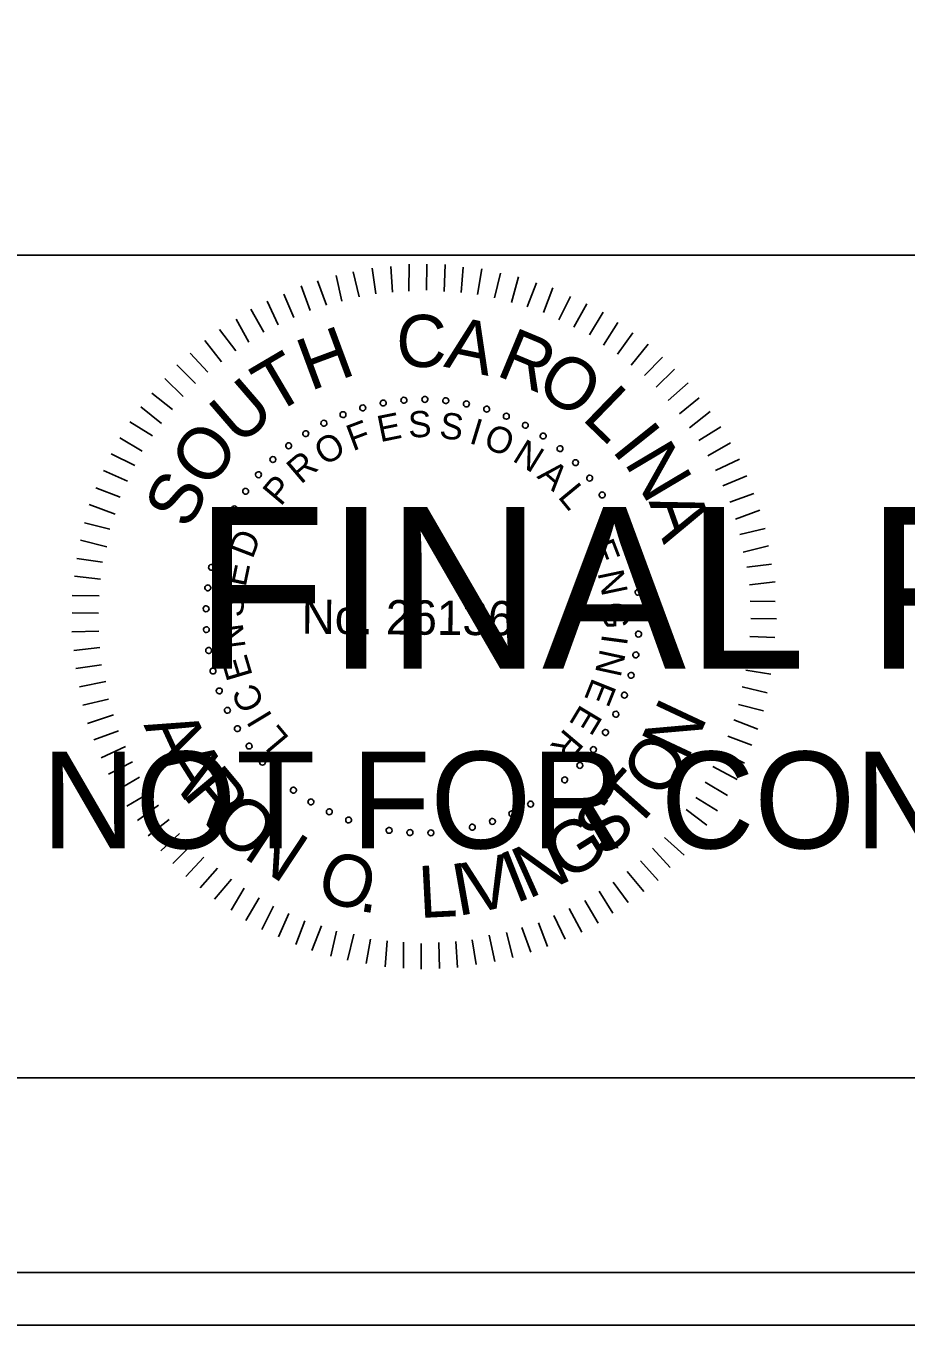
# Model space of a CAD drawing. Extents: x 967 to 1326, y 964 to 2304.
# Drawn here: x 1170.56 to 1189.3, y 1803.72 to 1831.36 of the extents above; entities that cross this region are included whole.
import ezdxf

# ---------------------------------------------------------------- set-up
doc = ezdxf.new("R2010")
doc.units = 0
for name, color, linetype in [('RD_PD_PaveShd', 7, 'Continuous'), ('RD_XS_Misc_Line', 7, 'Continuous'), ('RD_XS_PaveOvlay', 7, 'Continuous'), ('RD_XS_TX_Elev_EX', 7, 'Continuous'), ('RD_XS_TX_Elev_PR', 7, 'Continuous')]:
    doc.layers.add(name, color=color, linetype=linetype)

msp = doc.modelspace()

# ---------------------------------------------------------------- linework, layer by layer
at = {"layer": 'RD_PD_PaveShd'}
for p, q in [((996.114, 1826.486), (1323.886, 1826.486)), ((1323.886, 1808.983), (996.114, 1808.983))]:
    msp.add_line(p, q, dxfattribs=at)
at = {"layer": 'RD_XS_Misc_Line'}
for p, q in [((1178.01, 1825.663), (1177.93, 1826.209)), ((1178.364, 1825.699), (1178.33, 1826.244)), ((1178.717, 1825.719), (1178.722, 1826.295)), ((1179.093, 1825.739), (1179.098, 1826.292)), ((1179.469, 1825.713), (1179.489, 1826.288)), ((1179.829, 1825.687), (1179.872, 1826.231)), ((1180.174, 1825.646), (1180.271, 1826.19)), ((1176.964, 1825.419), (1176.769, 1825.935)), ((1177.287, 1825.508), (1177.169, 1826.054)), ((1177.657, 1825.597), (1177.53, 1826.128)), ((1180.535, 1825.573), (1180.662, 1826.102)), ((1180.902, 1825.478), (1181.045, 1826.022)), ((1181.231, 1825.384), (1181.428, 1825.896)), ((1176.264, 1825.156), (1176.053, 1825.657)), ((1176.61, 1825.306), (1176.423, 1825.83)), ((1181.584, 1825.265), (1181.78, 1825.786)), ((1181.905, 1825.109), (1182.154, 1825.606)), ((1175.624, 1824.846), (1175.352, 1825.332)), ((1175.933, 1825.005), (1175.699, 1825.506)), ((1182.226, 1824.953), (1182.506, 1825.45)), ((1175.308, 1824.634), (1175.036, 1825.12)), ((1182.562, 1824.789), (1182.85, 1825.27)), ((1175.03, 1824.445), (1174.681, 1824.9)), ((1182.86, 1824.572), (1183.163, 1825.053)), ((1183.158, 1824.378), (1183.484, 1824.828)), ((1174.729, 1824.217), (1174.372, 1824.665)), ((1183.447, 1824.145), (1183.811, 1824.587)), ((1174.435, 1823.997), (1174.062, 1824.399)), ((1183.729, 1823.92), (1184.116, 1824.316)), ((1174.172, 1823.753), (1173.776, 1824.148)), ((1183.98, 1823.672), (1184.368, 1824.061)), ((1173.909, 1823.479), (1173.52, 1823.858)), ((1184.232, 1823.394), (1184.657, 1823.767)), ((1173.684, 1823.197), (1173.242, 1823.546)), ((1184.475, 1823.108), (1184.892, 1823.45)), ((1173.451, 1822.9), (1173.009, 1823.256)), ((1184.687, 1822.807), (1185.128, 1823.156)), ((1173.257, 1822.64), (1172.776, 1822.936)), ((1173.039, 1822.312), (1172.559, 1822.6)), ((1184.885, 1822.544), (1185.355, 1822.832)), ((1185.081, 1822.213), (1185.56, 1822.493)), ((1172.883, 1822.006), (1172.379, 1822.256)), ((1185.24, 1821.904), (1185.756, 1822.145)), ((1172.727, 1821.677), (1172.215, 1821.904)), ((1185.399, 1821.573), (1185.907, 1821.791)), ((1172.571, 1821.333), (1172.051, 1821.53)), ((1185.549, 1821.226), (1186.057, 1821.414)), ((1172.461, 1820.974), (1171.91, 1821.178)), ((1185.669, 1820.865), (1186.185, 1821.06)), ((1172.351, 1820.652), (1171.807, 1820.787)), ((1185.759, 1820.541), (1186.297, 1820.667)), ((1172.286, 1820.276), (1171.727, 1820.419)), ((1185.832, 1820.165), (1186.371, 1820.298)), ((1172.191, 1819.955), (1171.647, 1820.029)), ((1185.906, 1819.842), (1186.436, 1819.906)), ((1172.15, 1819.587), (1171.598, 1819.653)), ((1185.964, 1819.473), (1186.51, 1819.53)), ((1172.124, 1819.234), (1171.548, 1819.239)), ((1185.977, 1819.12), (1186.514, 1819.115)), ((1172.105, 1818.866), (1171.545, 1818.871)), ((1185.997, 1818.751), (1186.542, 1818.747)), ((1172.118, 1818.482), (1171.542, 1818.471)), ((1185.971, 1818.368), (1186.508, 1818.348)), ((1172.138, 1818.136), (1171.585, 1818.072)), ((1185.952, 1818.022), (1186.497, 1817.949)), ((1172.173, 1817.768), (1171.627, 1817.688)), ((1185.888, 1817.655), (1186.417, 1817.566)), ((1172.262, 1817.414), (1171.701, 1817.296)), ((1185.808, 1817.302), (1186.345, 1817.175)), ((1172.321, 1817.037), (1171.774, 1816.911)), ((1185.729, 1816.926), (1186.265, 1816.792)), ((1172.425, 1816.707), (1171.871, 1816.519)), ((1185.634, 1816.597), (1186.146, 1816.401)), ((1172.53, 1816.36), (1172.007, 1816.173)), ((1185.508, 1816.253), (1186.013, 1816.057)), ((1172.681, 1816.029), (1172.165, 1815.788)), ((1172.831, 1815.705), (1172.323, 1815.441)), ((1185.352, 1815.924), (1185.857, 1815.675)), ((1185.188, 1815.603), (1185.7, 1815.33)), ((1172.982, 1815.374), (1172.497, 1815.094)), ((1185.024, 1815.274), (1185.498, 1814.987)), ((1173.194, 1815.042), (1172.709, 1814.762)), ((1184.822, 1814.946), (1185.288, 1814.658)), ((1173.384, 1814.78), (1172.936, 1814.453)), ((1184.62, 1814.687), (1185.055, 1814.353)), ((1173.612, 1814.478), (1173.164, 1814.129)), ((1184.403, 1814.389), (1184.814, 1814.033)), ((1173.832, 1814.177), (1173.437, 1813.812)), ((1184.155, 1814.092), (1184.574, 1813.72)), ((1174.091, 1813.945), (1173.689, 1813.541)), ((1183.899, 1813.864), (1184.28, 1813.454)), ((1174.35, 1813.674), (1173.97, 1813.263)), ((1183.644, 1813.597), (1184.024, 1813.18)), ((1174.64, 1813.442), (1174.275, 1813.022)), ((1174.937, 1813.209), (1174.58, 1812.782)), ((1183.358, 1813.37), (1183.715, 1812.944)), ((1175.212, 1813.014), (1174.932, 1812.549)), ((1182.764, 1812.952), (1183.059, 1812.482)), ((1183.065, 1813.141), (1183.384, 1812.709)), ((1175.525, 1812.812), (1175.245, 1812.331)), ((1175.83, 1812.633), (1175.588, 1812.136)), ((1182.463, 1812.755), (1182.743, 1812.269)), ((1176.159, 1812.477), (1175.94, 1811.98)), ((1181.8, 1812.431), (1182.041, 1811.93)), ((1182.124, 1812.581), (1182.396, 1812.08)), ((1176.503, 1812.321), (1176.307, 1811.816)), ((1176.855, 1812.211), (1176.651, 1811.69)), ((1177.177, 1812.1), (1177.05, 1811.572)), ((1180.791, 1812.07), (1180.926, 1811.54)), ((1181.122, 1812.175), (1181.31, 1811.652)), ((1181.476, 1812.28), (1181.664, 1811.771)), ((1177.545, 1812.036), (1177.409, 1811.484)), ((1177.897, 1811.933), (1177.808, 1811.412)), ((1178.25, 1811.892), (1178.207, 1811.34)), ((1178.603, 1811.866), (1178.598, 1811.313)), ((1178.978, 1811.84), (1178.974, 1811.295)), ((1179.355, 1811.86), (1179.365, 1811.307)), ((1179.715, 1811.88), (1179.749, 1811.327)), ((1180.061, 1811.915), (1180.149, 1811.393)), ((1180.423, 1812.012), (1180.541, 1811.458))]:
    msp.add_line(p, q, dxfattribs=at)
for centre, start, end in [((1178.168, 1823.337), 10.6038, 190.6038), ((1178.609, 1823.397), 5.0653, 185.0653), ((1178.609, 1823.397), 185.0653, 5.0653), ((1179.055, 1823.414), 359.5268, 179.5268), ((1179.055, 1823.414), 179.5268, 359.5268), ((1179.5, 1823.388), 353.9884, 173.9884), ((1177.312, 1823.091), 21.6807, 201.6807), ((1177.734, 1823.235), 16.1422, 196.1422), ((1177.734, 1823.235), 196.1422, 16.1422), ((1178.168, 1823.337), 190.6038, 10.6038), ((1179.5, 1823.388), 173.9884, 353.9884), ((1179.94, 1823.319), 168.4499, 348.4499), ((1179.94, 1823.319), 348.4499, 168.4499), ((1180.372, 1823.208), 162.9114, 342.9114), ((1180.372, 1823.208), 342.9114, 162.9114), ((1180.79, 1823.056), 337.373, 157.373), ((1176.906, 1822.908), 27.2191, 207.2191), ((1176.906, 1822.908), 207.2191, 27.2191), ((1177.312, 1823.091), 201.6807, 21.6807), ((1180.79, 1823.056), 157.373, 337.373), ((1181.193, 1822.864), 151.8345, 331.8345), ((1181.193, 1822.864), 331.8345, 151.8345), ((1176.52, 1822.686), 32.7576, 212.7576), ((1176.52, 1822.686), 212.7576, 32.7576), ((1181.574, 1822.634), 146.2961, 326.2961), ((1181.574, 1822.634), 326.2961, 146.2961), ((1176.156, 1822.428), 38.2961, 218.2961), ((1176.156, 1822.428), 218.2961, 38.2961), ((1181.932, 1822.368), 140.7576, 320.7576), ((1181.932, 1822.368), 320.7576, 140.7576), ((1175.82, 1822.135), 43.8345, 223.8345), ((1175.82, 1822.135), 223.8345, 43.8345), ((1182.263, 1822.069), 135.2191, 315.2191), ((1182.263, 1822.069), 315.2191, 135.2191), ((1175.513, 1821.812), 49.373, 229.373), ((1175.513, 1821.812), 229.373, 49.373), ((1182.563, 1821.74), 129.6807, 309.6807), ((1182.563, 1821.74), 309.6807, 129.6807), ((1175.239, 1821.461), 54.9114, 234.9114), ((1175.239, 1821.461), 234.9114, 54.9114), ((1182.83, 1821.383), 124.1422, 304.1422), ((1182.83, 1821.383), 304.1422, 124.1422), ((1175, 1821.085), 60.4499, 240.4499), ((1175, 1821.085), 240.4499, 60.4499), ((1183.061, 1821.002), 118.6038, 298.6038), ((1183.061, 1821.002), 298.6038, 118.6038), ((1174.798, 1820.687), 65.9884, 245.9884), ((1174.798, 1820.687), 245.9884, 65.9884), ((1183.255, 1820.601), 113.0653, 293.0653), ((1183.255, 1820.601), 293.0653, 113.0653), ((1174.636, 1820.272), 71.5268, 251.5268), ((1174.636, 1820.272), 251.5268, 71.5268), ((1183.408, 1820.182), 107.5268, 287.5268), ((1183.408, 1820.182), 287.5268, 107.5268), ((1174.514, 1819.843), 77.0653, 257.0653), ((1174.514, 1819.843), 257.0653, 77.0653), ((1183.521, 1819.751), 101.9884, 281.9884), ((1183.521, 1819.751), 281.9884, 101.9884), ((1174.435, 1819.405), 82.6038, 262.6038), ((1174.435, 1819.405), 262.6038, 82.6038), ((1183.592, 1819.311), 96.4499, 276.4499), ((1183.592, 1819.311), 276.4499, 96.4499), ((1174.398, 1818.961), 88.1422, 268.1422), ((1174.398, 1818.961), 268.1422, 88.1422), ((1183.619, 1818.866), 90.9114, 270.9114), ((1183.619, 1818.866), 270.9114, 90.9114), ((1174.404, 1818.515), 93.6807, 273.6807), ((1174.404, 1818.515), 273.6807, 93.6807), ((1183.604, 1818.421), 85.373, 265.373), ((1183.604, 1818.421), 265.373, 85.373), ((1174.453, 1818.072), 99.2191, 279.2191), ((1174.453, 1818.072), 279.2191, 99.2191), ((1183.546, 1817.979), 79.8345, 259.8345), ((1183.546, 1817.979), 259.8345, 79.8345), ((1174.545, 1817.636), 104.7576, 284.7576), ((1174.545, 1817.636), 284.7576, 104.7576), ((1183.445, 1817.545), 74.2961, 254.2961), ((1183.445, 1817.545), 254.2961, 74.2961), ((1174.678, 1817.211), 110.2961, 290.2961), ((1174.678, 1817.211), 290.2961, 110.2961), ((1183.303, 1817.122), 68.7576, 248.7576), ((1183.303, 1817.122), 248.7576, 68.7576), ((1174.852, 1816.8), 115.8345, 295.8345), ((1174.852, 1816.8), 295.8345, 115.8345), ((1183.121, 1816.716), 63.2191, 243.2191), ((1183.121, 1816.716), 243.2191, 63.2191), ((1175.065, 1816.409), 121.373, 301.373), ((1175.065, 1816.409), 301.373, 121.373), ((1182.9, 1816.328), 57.6807, 237.6807), ((1182.9, 1816.328), 237.6807, 57.6807), ((1175.314, 1816.039), 126.9114, 306.9114), ((1175.314, 1816.039), 306.9114, 126.9114), ((1182.643, 1815.964), 52.1422, 232.1422), ((1182.643, 1815.964), 232.1422, 52.1422), ((1175.598, 1815.696), 132.4499, 312.4499), ((1175.598, 1815.696), 312.4499, 132.4499), ((1182.353, 1815.627), 46.6038, 226.6038), ((1182.353, 1815.627), 226.6038, 46.6038), ((1175.914, 1815.381), 137.9884, 317.9884), ((1175.914, 1815.381), 317.9884, 137.9884), ((1182.03, 1815.319), 41.0653, 221.0653), ((1176.258, 1815.099), 143.5268, 323.5268), ((1176.258, 1815.099), 323.5268, 143.5268), ((1181.68, 1815.043), 35.5268, 215.5268), ((1182.03, 1815.319), 221.0653, 41.0653), ((1176.629, 1814.851), 149.0653, 329.0653), ((1176.629, 1814.851), 329.0653, 149.0653), ((1181.305, 1814.803), 29.9884, 209.9884), ((1181.305, 1814.803), 209.9884, 29.9884), ((1181.68, 1815.043), 215.5268, 35.5268), ((1177.021, 1814.639), 154.6038, 334.6038), ((1177.021, 1814.639), 334.6038, 154.6038), ((1180.908, 1814.6), 24.4499, 204.4499), ((1180.908, 1814.6), 204.4499, 24.4499), ((1177.432, 1814.467), 160.1422, 340.1422), ((1177.432, 1814.467), 340.1422, 160.1422), ((1177.858, 1814.335), 165.6807, 345.6807), ((1177.858, 1814.335), 345.6807, 165.6807), ((1178.294, 1814.245), 351.2191, 171.2191), ((1179.627, 1814.232), 7.8345, 187.8345), ((1180.065, 1814.313), 13.373, 193.373), ((1180.065, 1814.313), 193.373, 13.373), ((1180.494, 1814.436), 18.9114, 198.9114), ((1180.494, 1814.436), 198.9114, 18.9114), ((1178.294, 1814.245), 171.2191, 351.2191), ((1178.737, 1814.198), 356.7576, 176.7576), ((1178.737, 1814.198), 176.7576, 356.7576), ((1179.183, 1814.193), 2.2961, 182.2961), ((1179.183, 1814.193), 182.2961, 2.2961), ((1179.627, 1814.232), 187.8345, 7.8345)]:
    msp.add_arc(centre, 0.0627, start, end, dxfattribs=at)
at = {"layer": 'RD_XS_PaveOvlay'}
msp.add_lwpolyline([(967.409, 1803.72), (1326.285, 1803.72), (1326.285, 2023.72), (967.409, 2023.72)], close=True, dxfattribs=at)
at = {"layer": 'RD_XS_TX_Elev_EX'}
for points in [[(967.409, 1803.72), (1326.285, 1803.72), (1326.285, 2023.72), (967.409, 2023.72)], [(988.525, 1804.84), (1326.285, 1804.84), (1326.285, 2022.6), (988.525, 2022.6)]]:
    msp.add_lwpolyline(points, close=True, dxfattribs=at)

# ---------------------------------------------------------------- texts
at = {"layer": 'RD_XS_Misc_Line'}
for s, height, rotation, p in [('C', 1.11, 359.5482, (1178.442, 1824.108)), ('A', 1.11, 348.1981, (1179.439, 1824.115)), ('H', 1.11, 20.3637, (1176.614, 1823.587)), ('R', 1.11, 337.4344, (1180.541, 1823.937)), ('T', 1.11, 30.4992, (1175.828, 1823.072)), ('O', 1.108, 326.5869, (1181.366, 1823.609)), ('U', 1.11, 40.8022, (1175.102, 1822.403)), ('L', 1.11, 315.9488, (1182.373, 1823.003)), ('E', 0.557, 11.4103, (1178.103, 1822.503)), ('S', 0.557, 2.208, (1178.709, 1822.601)), ('S', 0.557, 352.6608, (1179.346, 1822.599)), ('O', 1.11, 52.0267, (1174.435, 1821.474)), ('F', 0.557, 20.6127, (1177.52, 1822.309)), ('I', 0.557, 343.1136, (1179.975, 1822.491)), ('O', 0.557, 338.4392, (1180.274, 1822.401)), ('I', 1.11, 308.6613, (1183.011, 1822.338)), ('O', 0.557, 30.8477, (1176.917, 1821.987)), ('N', 0.557, 328.2042, (1180.896, 1822.12)), ('N', 1.11, 300.7037, (1183.285, 1822.075)), ('R', 0.557, 40.3949, (1176.415, 1821.594)), ('A', 0.557, 318.657, (1181.424, 1821.762)), ('S', 1.108, 63.2511, (1174.029, 1820.619)), ('P', 0.557, 49.9421, (1175.985, 1821.124)), ('L', 0.557, 309.4546, (1181.869, 1821.339)), ('A', 1.11, 289.4792, (1183.814, 1821.243)), ('D', 0.557, 69.0364, (1175.386, 1820.003)), ('E', 0.557, 291.049, (1182.53, 1820.307)), ('E', 0.557, 78.2388, (1175.238, 1819.407)), ('N', 0.557, 281.8466, (1182.728, 1819.726)), ('S', 0.557, 87.786, (1175.187, 1818.772)), ('No. 26136', 0.7311, 359.5268, (1176.429, 1818.43)), ('G', 0.557, 272.2995, (1182.833, 1819.097)), ('N', 0.557, 97.3332, (1175.242, 1818.137)), ('I', 0.557, 262.4084, (1182.83, 1818.437)), ('E', 0.557, 106.5355, (1175.394, 1817.541)), ('N', 0.557, 257.7339, (1182.789, 1818.127)), ('C', 0.557, 116.4266, (1175.661, 1816.938)), ('E', 0.557, 248.1867, (1182.628, 1817.511)), ('I', 0.557, 121.1011, (1175.823, 1816.67)), ('E', 0.557, 238.9844, (1182.378, 1816.949)), ('N', 1.105, 64.8922, (1184.632, 1815.684)), ('A', 1.105, 294.7297, (1173.062, 1816.486)), ('L', 0.557, 129.9595, (1176.187, 1816.204)), ('R', 0.557, 229.782, (1182.041, 1816.435)), ('O', 1.105, 56.2059, (1184.102, 1814.874)), ('A', 1.105, 302.2892, (1173.414, 1815.72)), ('R', 1.105, 309.8487, (1173.865, 1815.007)), ('T', 1.105, 48.2685, (1183.515, 1814.211)), ('O', 1.105, 317.7861, (1174.434, 1814.33)), ('S', 1.105, 40.3311, (1182.842, 1813.636)), ('N', 1.105, 326.4725, (1175.158, 1813.686)), ('G', 1.105, 32.0198, (1182.059, 1813.14)), ('N', 1.105, 24.0824, (1181.252, 1812.776)), ('O', 1.105, 342.3472, (1176.697, 1812.82)), ('V', 1.105, 12.7741, (1180.033, 1812.457)), ('I', 1.105, 21.4605, (1180.976, 1812.681)), ('L', 1.105, 2.9677, (1178.943, 1812.379)), ('I', 1.105, 10.1523, (1179.743, 1812.418)), ('.', 1.105, 351.0336, (1177.623, 1812.536))]:
    msp.add_text(s, height=height, rotation=rotation, dxfattribs=at).set_placement(p)
at = {"layer": 'RD_XS_TX_Elev_PR'}
for s, height, p in [('FINAL PLANS', 3.4375, (1174.145, 1817.685)), ('NOT FOR CONSTRUCTION', 2.0625, (1170.901, 1813.86))]:
    msp.add_text(s, height=height, dxfattribs=at).set_placement(p)

doc.saveas('drawing.dxf')
